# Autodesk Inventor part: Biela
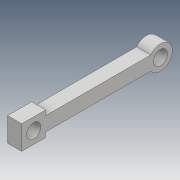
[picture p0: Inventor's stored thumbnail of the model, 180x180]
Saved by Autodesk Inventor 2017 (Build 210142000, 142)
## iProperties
Created: 2019-09
Part Number: Biela
Material: Generic
Document SubType Name: Modeling
Designer: user
Density: 1 g/cm^3
Appearance: Default
Author: user
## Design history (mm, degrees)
sketch "Sketch1"
  geometry: L1 (8.5, 8.5)-(-8.5, 8.5); L2 (-8.5, 8.5)-(-8.5, -8.5); L3 (-8.5, -8.5)-(8.5, -8.5); L4 (84.41, -5)-(8.5, -5); L5 (84.41, 5)-(8.5, 5); L6 (8.5, -8.5)-(8.5, -5); L7 (8.5, 5)-(8.5, 8.5); C1 r 5 at (0, 0); C2 r 5 at (90, 0); A1 r 7.5 centre (90, 0) between (84.41, -5) and (84.41, 5); 4 further points
  constraints: 14 end point, 3 centre point, 3 parallel, 3 perpendicular, 2 coincident, 2 midpoint, 2 point on circle, 1 horizontal, 1 horizontal alignment, 1 tangent, 1 vertical alignment
  dimensions: "d0" = 90 distance of C2.centre point (0, 0); "d1" = 10 diameter of C1; "d3" = 17 distance of L3.end L2.end; "d4" = 17 distance of L2.end L1.end; "d5" = 10 diameter of C2; "d6" = 15 diameter of A1
extrude "Extrusion1" new body sketch "Sketch1" distance "d9" = 10; taper "d10" = 0 deg
sketch "Sketch2"
  geometry: C1 r 5 at (0, 90) reference; C2 r 8.5 at (0, 90); C3 r 6.403 at (0, 90); 1 further point
  constraints: 2 centre point, 2 coincident
  dimensions: "d11" = 17 diameter of C2
extrude "Extrusion2" join sketch "Sketch2" distance "d12" = 10; taper "d13" = 0 deg
body "Solid1"
